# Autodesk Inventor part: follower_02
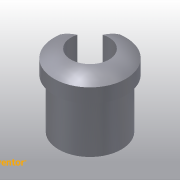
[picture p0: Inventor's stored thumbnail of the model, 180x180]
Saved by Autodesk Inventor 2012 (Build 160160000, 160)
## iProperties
Shininess: 64.0
Length Units: 11272
Angle Units: 11279
Time Units: 11290
Mass Units: 11286
Length Display Precision: 3
Angle Display Precision: 2
Compacted: True
Company: Autodesk
Created: 2002-07
Part Number: follower_02
Document SubType Name: Modeling
Designer: Lieven Grauls
Stock Number: follower_02
Project: Valve Techcamp 2008
Density: 1 g/cm^3
Mass: 5.50036 g
Surface Area: 30.9672 cm^2
Volume: 5.50036 cm^3
Material: Default
Density: 0.0
Volumn: 0.0
Area: 0.0
PropertySet Name: Model Information
Control State: 0
Master: False
Checked Out: False
Author: Lieven Grauls
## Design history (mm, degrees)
sketch "Sketch1"
  geometry: L1 (6.477, 0)-(11.102, 0); L2 (11.102, 0)-(11.102, 17.463); L3 (11.102, 17.463)-(12.7, 17.463); L4 (12.7, 17.463)-(12.7, 22.463); L5 (6.477, 0)-(6.477, 6.35); L6 (6.477, 6.35)-(6.747, 6.35); L7 (6.747, 6.35)-(6.747, 25.4); L8 (0, 30.748)-(0, -5.125) reference; A1 r 22.225 centre (0, 4.224) between (12.7, 22.463) and (6.747, 25.4); 1 further point
  constraints: 14 end point, 3 parallel, 2 perpendicular, 2 point on circle, 1 centre point, 1 horizontal, 1 horizontal alignment, 1 point on line
  dimensions: "d0" = 22.225 radius of A1; "d1" = 12.954 diameter of L5 L8; "d2" = 22.20468 diameter of L2 L8; "d3" = 25.4 diameter of L4 L8; "d5" = 13.49375 diameter of L7 L8; "d6" = 17.4625 distance between parallel lines of L1 L3; "d9" = 25.4 distance from line of L1 L7.end; "d10" = 19.05 distance of L7.end L6.end
revolve "Revolution1" sketch "Sketch1" stored, may be unused: angle "d11" = 90 deg
sketch "Sketch2"
  geometry: L1 (-12.542, -2)-(-2, -2); L2 (-2, -2)-(-2, -12.542); L3 (0, 18.09)-(0, -19.641); L4 (-19.641, 0)-(18.09, 0); C1 r 6.477 at (0, 0) reference; C2 r 11.102 at (0, 0) reference; A1 r 12.7 centre (0, 0) between (-12.542, -2) and (-2, -12.542); A2 r 12.7 centre (0, 0) between (-12.542, -2) and (-2, -12.542); 1 further point
  constraints: 8 end point, 4 point on circle, 2 centre point, 1 coincident, 1 horizontal, 1 perpendicular
  dimensions: "d12" = 2 distance between parallel lines of L1 L4; "d13" = 2 distance between parallel lines of L3 L2 (= d12)
extrude "Extrusion1" cut sketch "Sketch2" stored distance "d14" = 25.4; taper "d15" = 0 deg
node "Volumenkörper1"
node "Volumenkörpern"
node "Oberflächenkörpern"
